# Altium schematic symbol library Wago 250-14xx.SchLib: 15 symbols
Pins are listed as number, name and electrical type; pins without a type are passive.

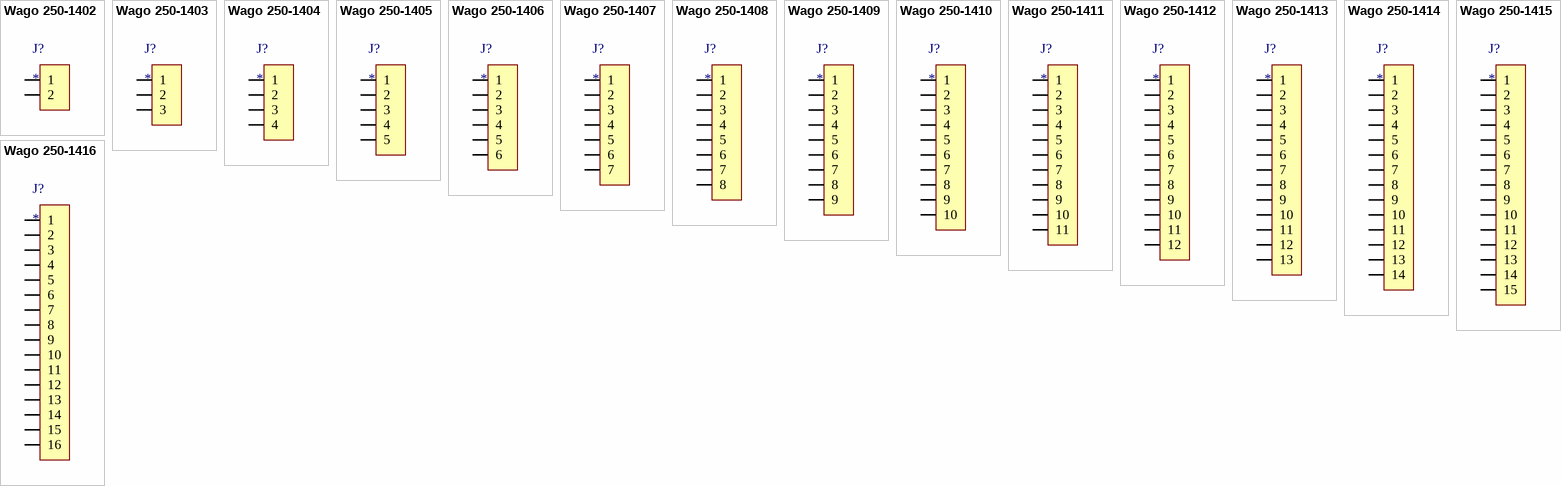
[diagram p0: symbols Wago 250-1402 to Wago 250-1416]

## Wago 250-1402
designator J?
footprint Wago 250-1402
pins: 1, 2

## Wago 250-1403
designator J?
footprint Wago 250-1403
pins: 1, 2, 3

## Wago 250-1404
designator J?
footprint Wago 250-1404
pins: 1, 2, 3, 4

## Wago 250-1405
designator J?
footprint Wago 250-1405
pins: 1, 2, 3, 4, 5

## Wago 250-1406
designator J?
footprint Wago 250-1406
pins: 1, 2, 3, 4, 5, 6

## Wago 250-1407
designator J?
footprint Wago 250-1407
pins: 1, 2, 3, 4, 5, 6, 7

## Wago 250-1408
designator J?
footprint Wago 250-1408
pins: 1, 2, 3, 4, 5, 6, 7, 8

## Wago 250-1409
designator J?
footprint Wago 250-1409
pins: 1, 2, 3, 4, 5, 6, 7, 8, 9

## Wago 250-1410
designator J?
footprint Wago 250-1410
pins: 1, 2, 3, 4, 5, 6, 7, 8, 9, 10

## Wago 250-1411
designator J?
footprint Wago 250-1411
pins: 1, 2, 3, 4, 5, 6, 7, 8, 9, 10, 11

## Wago 250-1412
designator J?
footprint Wago 250-1412
pins: 1, 2, 3, 4, 5, 6, 7, 8, 9, 10, 11, 12

## Wago 250-1413
designator J?
footprint Wago 250-1413
pins: 1, 2, 3, 4, 5, 6, 7, 8, 9, 10, 11, 12, 13

## Wago 250-1414
designator J?
footprint Wago 250-1414
pins: 1, 2, 3, 4, 5, 6, 7, 8, 9, 10, 11, 12, 13, 14

## Wago 250-1415
designator J?
footprint Wago 250-1415
pins: 1, 2, 3, 4, 5, 6, 7, 8, 9, 10, 11, 12, 13, 14, 15

## Wago 250-1416
designator J?
footprint Wago 250-1416
pins: 1, 2, 3, 4, 5, 6, 7, 8, 9, 10, 11, 12, 13, 14, 15, 16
